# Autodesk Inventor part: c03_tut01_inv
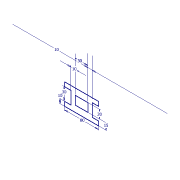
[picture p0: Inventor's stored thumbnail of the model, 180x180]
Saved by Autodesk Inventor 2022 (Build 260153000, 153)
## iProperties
Created: 2017-04
Part Number: c03_tut01_inv
Material: Generic
Document SubType Name: Modeling
Designer: CADCIM 00
Density: 1 g/cm^3
Appearance: Default
Author: CADCIM 00
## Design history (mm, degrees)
sketch "Sketch2"
  geometry: L1 (0, 0)-(0, 10); L2 (0, 10)-(-15, 10); L3 (-15, 10)-(-15, 40); L4 (-15, 40)-(0, 40); L5 (0, 40)-(0, 50); L6 (0, 50)-(-80, 50); L7 (-80, 50)-(-80, 40); L8 (-80, 40)-(-65, 40); L9 (-65, 40)-(-65, 10); L10 (-65, 10)-(-80, 10); L11 (-80, 0)-(0, 0); L12 (-80, 10)-(-80, 0); L13 (-25, 35)-(-55, 35); L14 (-55, 35)-(-55, 15); L15 (-55, 15)-(-25, 15); L16 (-25, 15)-(-25, 35)
  constraints: 32 end point, 8 perpendicular, 8 point on line, 3 parallel, 2 collinear, 1 horizontal, 1 vertical
  dimensions: "d0" = 80 distance of L11.start L1.start; "d1" = 10 distance of L1.start L1.end; "d2" = 30 distance of L2.end L3.end; "d3" = 10 distance between parallel lines of L16 L3; "d4" = 10 distance between parallel lines of L9 L14; "d5" = 15 distance between parallel lines of L15 L11; "d6" = 20 distance of L13.end L14.end; "d7" = 30 distance of L13.start L13.end
